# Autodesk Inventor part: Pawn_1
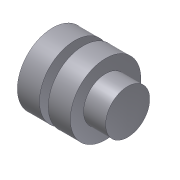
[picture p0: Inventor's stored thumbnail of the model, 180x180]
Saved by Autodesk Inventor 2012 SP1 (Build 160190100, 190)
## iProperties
Created: 2006-03
Part Number: Pawn_1
Document SubType Name: Modeling
Material: Stainless Steel, 440C
Mass: 19.8431 g
Surface Area: 13.6973 cm^2
Volume: 2.5604 cm^3
Density: 7.75 g/cm^3
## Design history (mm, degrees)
sketch "Sketch1"
  geometry: L1 (0, 0)-(5, 0); L2 (5, 0)-(5, 5); L3 (5, 5)-(0, 5); L4 (0, 5)-(0, 0); L5 (5, 8)-(10, 8); L6 (10, 8)-(10, 0); L7 (10, 0)-(5, 0); L8 (5, 0)-(5, 8); L9 (10, 5)-(12, 5); L10 (12, 5)-(12, 0); L11 (12, 0)-(10, 0); L12 (10, 0)-(10, 5); L13 (-5.1, 0)-(18.7, 0) reference; L14 (12, 8)-(17, 8); L15 (17, 8)-(17, 0); L16 (17, 0)-(12, 0); L17 (12, 0)-(12, 8)
  constraints: 32 end point, 8 parallel, 7 collinear, 4 horizontal, 4 perpendicular, 1 point on line
  dimensions: "d0" = 5 distance of L2.end L3.end; "d1" = 5 distance of L3.end L1.start; "d2" = 8 distance between parallel lines of L13 L5; "d3" = 2 distance of L9.start L9.end; "d4" = 5 distance of L14.start L14.end; "d5" = 5 distance between parallel lines of L9 L13
revolve "Revolution1" sketch "Sketch1" stored, may be unused: angle "d6" = 90 deg
body "Solid1"
